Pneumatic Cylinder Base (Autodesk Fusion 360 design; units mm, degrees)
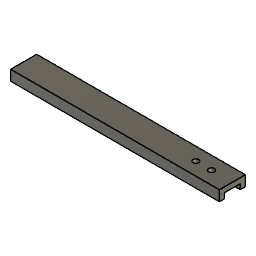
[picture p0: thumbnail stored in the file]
sketch "Sketch1" plane through (0, 0, 0) normal (0, 0, 1) x axis (1, 0, 0)
  line L1 (35, 12.5) -> (-165, 12.5)
  line L2 (35, -12.5) -> (35, 12.5)
  line L3 (-165, -12.5) -> (35, -12.5)
  line L4 (-165, 12.5) -> (-165, -12.5)
  line L5 (-165, 0) -> (35, 0)
  circle C1 centre (0, 0) radius 2.75
  circle C2 centre (15, 0) radius 2.75
  point P1 (0, 0)
  point P2 (0, 0)
  point P3 (15, 0)
  point P8 (35, 0)
  point P9 (-165, 0)
  point P5 (35, 12.5)
  point P6 (35, -12.5)
  point P7 (-165, -12.5)
  coincident P1 P2
  horizontal P2 P3
  equal C1 C2
  horizontal L1
  vertical L2
  horizontal L3
  vertical L4
  midpoint L2 P8
  midpoint L4 P9
  coincident P2 L5
  dimension "d1" diameter C1 = 5.5
  dimension "d2" distance P2 P3 = 15
  dimension "d3" distance P3 L2 = 20
  dimension "d4" distance P5 P6 = 25
  dimension "d5" distance P6 P7 = 200
extrude "Extrude1" new body sketch "Sketch1" profile of C1 C2 L1 L2 L3 L4 against normal blind 5
sketch "Sketch2" plane through (35, 0, 0) normal (1, 0, 0) x axis (0, 1, 0)
  line L1 (-12.5, 0) -> (12.5, 0)
  line L2 (-12.5, -5) -> (-12.5, 0)
  line L3 (12.5, -5) -> (-12.5, -5)
  line L4 (12.5, 0) -> (12.5, -5)
  line L5 (-7.5, -5) -> (-12.5, -5)
  line L6 (-7.5, -10) -> (-7.5, -5)
  line L7 (-12.5, -10) -> (-7.5, -10)
  line L8 (-12.5, -5) -> (-12.5, -10)
  line L9 (7.5, -5) -> (12.5, -5)
  line L10 (7.5, -10) -> (7.5, -5)
  line L11 (12.5, -10) -> (7.5, -10)
  line L12 (12.5, -5) -> (12.5, -10)
  point P4 (-12.5, -5)
  point P6 (-12.5, -5)
  point P5 (12.5, -5)
  point P10 (12.5, -5)
  point P8 (-7.5, -10)
  point P9 (-12.5, -10)
  horizontal L5
  vertical L6
  horizontal L7
  vertical L8
  coincident P4 P6
  horizontal L9
  vertical L10
  horizontal L11
  vertical L12
  coincident P5 P10
  equal L7 L11
  collinear L7 L11
  dimension "d8" distance P8 P9 = 5
  dimension "d9" distance P6 P9 = 5
extrude "Extrude2" add sketch "Sketch2" profile of L3 L5 L6 L7 L8 L9 L10 L11 L12 to an object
